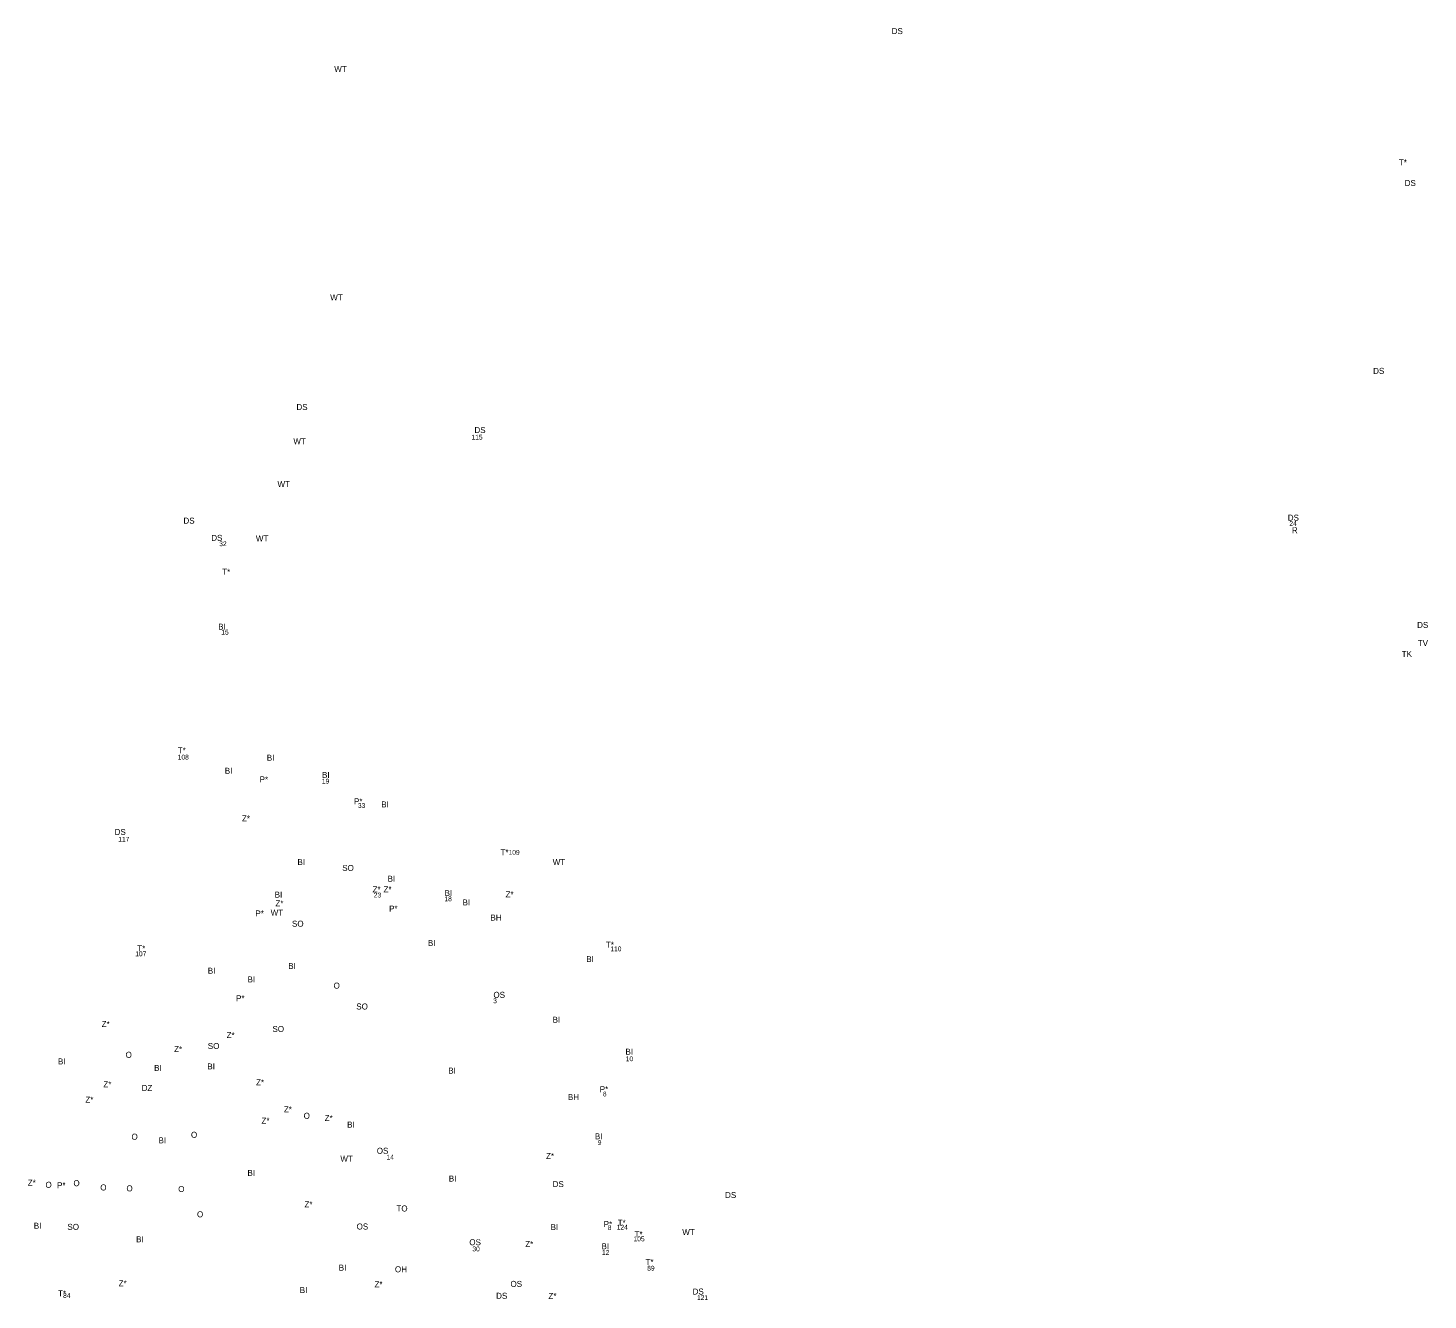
# Model space of a CAD drawing. Extents: x -521559 to -516922, y -1189648 to -1185402.
# Drawn here: x -519252 to -516922, y -1187519 to -1185402 of the extents above; entities that cross this region are included whole.
import ezdxf

# ---------------------------------------------------------------- set-up
doc = ezdxf.new("R2010")
doc.units = 0
for name, color, linetype in [('bydleni_n', 7, 'Continuous'), ('bydleni_s', 7, 'Continuous'), ('fpl_id', 7, 'Continuous'), ('rekreace_s', 7, 'Continuous'), ('s_zelen_n', 7, 'Continuous'), ('s_zelen_s', 7, 'Continuous'), ('sm_vyuziti_s', 7, 'Continuous'), ('v_infrastr_n', 7, 'Continuous'), ('v_infrastr_s', 7, 'Continuous'), ('voda_s', 7, 'Continuous')]:
    doc.layers.add(name, color=color, linetype=linetype)

msp = doc.modelspace()

# ---------------------------------------------------------------- texts
at = {"layer": 'bydleni_n'}
for p in [(-518935.7, -1186403.2), (-518762.9, -1186649.9), (-518558.9, -1186846.4), (-518257.9, -1187110.5), (-518308.9, -1187251.3), (-518297.8, -1187434.2)]:
    msp.add_text('BI', height=10, dxfattribs=at).set_placement(p)
at = {"layer": 'bydleni_s'}
for s, p in [('BI', (-518854.8, -1186621.3)), ('BI', (-518924.7, -1186643.1)), ('BI', (-518664.4, -1186699)), ('BI', (-518803.8, -1186795)), ('BI', (-518653.8, -1186822.7)), ('BI', (-518841.7, -1186849.1)), ('BI', (-518529, -1186862.2)), ('BH', (-518482.7, -1186887.3)), ('BI', (-518586.7, -1186929.5)), ('BI', (-518819.1, -1186967.8)), ('BI', (-518323.2, -1186956.5)), ('BI', (-518953, -1186975.7)), ('BI', (-518886.8, -1186990.3)), ('BI', (-518379.2, -1187057.4)), ('BI', (-519202.4, -1187126.7)), ('BI', (-518953.8, -1187135.1)), ('BI', (-519042.3, -1187137.5)), ('BI', (-518552.8, -1187142)), ('BH', (-518353.8, -1187185.9)), ('BI', (-518721.1, -1187231.8)), ('BI', (-519035, -1187258)), ('BI', (-518887, -1187312.2)), ('BI', (-518551.9, -1187321.6)), ('BI', (-519242.6, -1187400.1)), ('BI', (-518382.5, -1187402.3)), ('BI', (-519072.3, -1187422.6)), ('BI', (-518735.1, -1187469.8)), ('BI', (-518800, -1187507.3))]:
    msp.add_text(s, height=10, dxfattribs=at).set_placement(p)
at = {"layer": 'fpl_id'}
for s, p in [('115', (-518514.2, -1186087)), ('24', (-517153.1, -1186230.5)), ('32', (-518934, -1186264.3)), ('15', (-518930.5, -1186411.4)), ('108', (-519003, -1186619.3)), ('19', (-518763.2, -1186659.4)), ('33', (-518703.2, -1186699.9)), ('117', (-519102, -1186756)), ('109', (-518452.5, -1186777.8)), ('23', (-518676.8, -1186848.9)), ('18', (-518559.2, -1186855.2)), ('107', (-519073.7, -1186946.7)), ('110', (-518283.1, -1186938.4)), ('3', (-518478.1, -1187024.8)), ('10', (-518257.5, -1187121.3)), ('6', (-518295.6, -1187180)), ('9', (-518304, -1187260.7)), ('14', (-518655.5, -1187285)), ('8', (-518287.4, -1187402.3)), ('124', (-518272.5, -1187401.5)), ('30', (-518512.7, -1187437.7)), ('105', (-518244.5, -1187421)), ('12', (-518297.1, -1187443.7)), ('89', (-518221.8, -1187469.8)), ('84', (-519193.8, -1187515.2)), ('121', (-518138.9, -1187518.7))]:
    msp.add_text(s, height=8, dxfattribs=at).set_placement(p)
at = {"layer": 'rekreace_s'}
msp.add_text('R', height=10, dxfattribs=at).set_placement((-517149, -1186242.7))
at = {"layer": 's_zelen_n'}
msp.add_text('Z*', height=10, dxfattribs=at).set_placement((-518678.8, -1186840.5))
at = {"layer": 's_zelen_s'}
for p in [(-518896.2, -1186722.4), (-518660.6, -1186840.4), (-518457.5, -1186848.8), (-518840.5, -1186863.6), (-519129.6, -1187064.3), (-518921.7, -1187082.9), (-519009.1, -1187106.2), (-519126.8, -1187164.6), (-518872.7, -1187161.4), (-519156.7, -1187190.2), (-518826.3, -1187206.4), (-518863.7, -1187225.3), (-518758.5, -1187220.9), (-518390.1, -1187283.9), (-519252.6, -1187328.5), (-518792.2, -1187364.6), (-518424.7, -1187430.5), (-519101.3, -1187495.7), (-518675.5, -1187497.6), (-518386.1, -1187516.8)]:
    msp.add_text('Z*', height=10, dxfattribs=at).set_placement(p)
at = {"layer": 'sm_vyuziti_s'}
for p in [(-518729.3, -1186804.7), (-518812.9, -1186897.5), (-518705.9, -1187035.3), (-518845.4, -1187072.7), (-518953, -1187101), (-519186.6, -1187402)]:
    msp.add_text('SO', height=10, dxfattribs=at).set_placement(p)
at = {"layer": 'v_infrastr_n'}
for s, p in [('DS', (-518509.3, -1186076.1)), ('DS', (-517155.8, -1186221.9)), ('DS', (-518947.2, -1186255.5)), ('T*', (-519003, -1186609)), ('P*', (-518709.8, -1186693.9)), ('DS', (-519108.1, -1186744.9)), ('T*', (-518465.9, -1186778.7)), ('T*', (-519070.3, -1186938.6)), ('T*', (-518290.5, -1186932.5)), ('OS', (-518477.7, -1187015.9)), ('P*', (-518300.8, -1187172.9)), ('OS', (-518671.8, -1187275.4)), ('P*', (-518294.3, -1187397.3)), ('T*', (-518270.9, -1187395)), ('T*', (-518242.9, -1187414.4)), ('OS', (-518517.8, -1187427.6)), ('T*', (-518224.7, -1187460.3)), ('DS', (-518146.3, -1187509.6)), ('T*', (-519202.2, -1187512.5))]:
    msp.add_text(s, height=10, dxfattribs=at).set_placement(p)
at = {"layer": 'v_infrastr_s'}
for s, p in [('DS', (-517815, -1185412.2)), ('T*', (-516970.9, -1185630.6)), ('DS', (-516961.3, -1185665)), ('DS', (-517013.7, -1185977.6)), ('DS', (-518805.5, -1186037.8)), ('DS', (-518993.5, -1186226.9)), ('T*', (-518928.9, -1186311.9)), ('DS', (-516940.5, -1186400.4)), ('TV', (-516939.5, -1186430.6)), ('TK', (-516966.2, -1186448.7)), ('P*', (-518866.8, -1186657.4)), ('P*', (-518873.8, -1186880.5)), ('P*', (-518651.3, -1186872.4)), ('O', (-518743.7, -1187000.5)), ('P*', (-518906, -1187021.6)), ('O', (-519089.8, -1187115.7)), ('DZ', (-519063, -1187170.7)), ('O', (-518793.5, -1187217.2)), ('O', (-519080, -1187252)), ('O', (-518981, -1187248.8)), ('O', (-519223.1, -1187332)), ('P*', (-519203.8, -1187332.9)), ('O', (-519176.6, -1187329.3)), ('O', (-519131.9, -1187336.4)), ('O', (-519088.4, -1187338)), ('O', (-519002.2, -1187339.1)), ('DS', (-518379.2, -1187330.8)), ('DS', (-518092.2, -1187349)), ('O', (-518971, -1187381.1)), ('TO', (-518639.1, -1187371.4)), ('OS', (-518705.4, -1187401.4)), ('OH', (-518641.6, -1187472.6)), ('OS', (-518449.3, -1187496.9)), ('DS', (-518473.2, -1187516.7))]:
    msp.add_text(s, height=10, dxfattribs=at).set_placement(p)
at = {"layer": 'voda_s'}
for p in [(-518742.6, -1185475.1), (-518749.3, -1185855.3), (-518810.6, -1186094.6), (-518837, -1186166.1), (-518873, -1186256.5), (-518379, -1186795.1), (-518848.4, -1186879), (-518732.4, -1187288.7), (-518163.4, -1187410.8)]:
    msp.add_text('WT', height=10, dxfattribs=at).set_placement(p)

doc.saveas('drawing.dxf')
